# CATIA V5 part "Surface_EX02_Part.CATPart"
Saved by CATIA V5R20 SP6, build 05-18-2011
Part number: Surface_EX02_Part
Bounding box of the stored display mesh (mm): x -11.2 to 32.635, y -54.492 to 10.43, z -5 to 39.701
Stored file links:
  C:\Work\#01 CATIA Lecture Materials\#299 TOYOTA CATIA V5\TOYOTA_CATIA\LCS\Surface\Surface EX02\Surface_EX02_Part.CATPart
  C:\Work\#01 CATIA Lecture Materials\#299 TOYOTA CATIA V5\TOYOTA_CATIA\LCS\Surface\Surface EX02\Surface_EX02.CATProduct
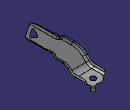
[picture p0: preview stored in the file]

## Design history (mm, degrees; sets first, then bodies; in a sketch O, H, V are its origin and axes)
Set1
  Point1: linked copy from another document
  Line1 to Line3: linked copy from another document
  Point2: linked copy from another document
  Line4 to Line6: linked copy from another document
Set2 "Base"
  Sketch1 on Line6, origin (25, -50, 35), H (0, 0.7071, 0.7071), V (0.5779, -0.5771, 0.5771)
    line L1 (0, 50) -> (0, -150)
    point P1 (0, 50)
    point P2 (0, -150)
    distance P1 P2 = 200
    distance H P2 = 150
    coincidence: P1 V
    vertical: L1 V
  Sketch2 on Line3, origin (0, 0, 0), H (0, 1, 0), V (0, 0, 1)
    line L1 (-150, 0) -> (50, 0)
    point P1 (-150, 0)
    point P2 (50, 0)
    distance P2 P1 = 200
    distance V P1 = 150
    coincidence: P1 H
    horizontal: L1 H
  Extrude1: Lim1 200, Lim2 200, Element1 Sketch2
  Extrude2: Lim1 200, Lim2 200, Element1 Sketch1
Set3 "Base Cut"
  Sketch3 on Line5, origin (25, -50, 35), H (-0.8161, -0.4086, 0.4086), V (0.5779, -0.5771, 0.5771)
    point P1 (-41.5, -30)
    line L1 (-41.5, -30) -> (-9.3787, 2.1213)
    point P2 (-8.5, 3)
    line L2 (-7.2574, 3) -> (7.2574, 3)
    point P3 (8.5, 3)
    line L3 (9.3787, 2.1213) -> (41.5, -30)
    point P4 (41.5, -30)
    arc A1 centre (-7.2574, 0) radius 3 from (-9.3787, 2.1213) to (-7.2574, 3) cw
    construction line L4 (-9.3787, 2.1213) -> (-8.5, 3)
    construction line L5 (-8.5, 3) -> (-7.2574, 3)
    arc A2 centre (7.2574, 0) radius 3 from (7.2574, 3) to (9.3787, 2.1213) cw
    construction line L6 (7.2574, 3) -> (8.5, 3)
    construction line L7 (8.5, 3) -> (9.3787, 2.1213)
    distance P2 P3 = 17
    distance L2 H = 3
    distance H P1 = 30
    distance H P4 = 30
    radius A1 = 3
    radius A2 = 3 {= Sketch3.radius(A1)}
    angle L2 L1 = 45
    angle L2 L3 = 45
    horizontal: L2 H
    symmetry: P2 P3 V
    coincidence: L1 P2, L2 P2, L1 L4, L2 L5, L2 P3, L3 P3, L2 L6, L3 L7
    tangency: A1 L1, A1 L2, A2 L2, A2 L3
  Sketch4 on Line3, origin (0, 0, 0), H (0, 1, 0), V (-1, 0, 0)
    arc A1 centre (0, 0) radius 8.5 from (7.9288, -3.0633) to (3.9391, 7.5322) ccw
    line L1 (2.8659, -10.8764) -> (2.8659, -50)
    construction line L2 (0, 0) -> (12.6476, -12.6476)
    line L3 (8.3802, -5.1982) -> (10.4298, -7.2478)
    line L4 (10.4298, -7.2478) -> (7.2478, -10.4298)
    line L5 (7.2478, -10.4298) -> (6.2802, -9.4621)
    reference projected point E1 (0, 0) from Point1
    point P4 (2.8659, 8.0023)
    point P5 (2.8659, -50)
    arc A2 centre (4.8659, -10.8764) radius 2 from (6.2802, -9.4621) to (2.8659, -10.8764) ccw
    construction line L6 (6.2802, -9.4621) -> (2.8659, -6.0479)
    construction line L7 (2.8659, -6.0479) -> (2.8659, -10.8764)
    line L8 (2.8659, 9.3044) -> (2.8659, 50)
    point P10 (2.8659, 50)
    arc A3 centre (4.8659, 9.3044) radius 2 from (3.9391, 7.5322) to (2.8659, 9.3044) cw
    construction arc A4 centre (0, 0) radius 8.5 from (3.9391, 7.5322) to (2.8659, 8.0023) ccw
    construction line L9 (2.8659, 8.0023) -> (2.8659, 9.3044)
    arc A5 centre (9.7944, -3.784) radius 2 from (7.9288, -3.0633) to (8.3802, -5.1982) ccw
    construction arc A6 centre (0, 0) radius 8.5 from (7.387, -4.205) to (7.9288, -3.0633) ccw
    construction line L10 (7.387, -4.205) -> (8.3802, -5.1982)
    radius A1 = 8.5
    distance L1 V = 2.8659
    angle L2 H = 45
    distance L3 L5 = 4.5
    distance L4 E1 = 12.5
    radius A2 = 2
    radius A3 = 2
    radius A5 = 2
    distance H P10 = 50
    distance P5 H = 50
    vertical: L1 V
    perpendicularity: L4 L3
    parallelism: L5 L2
    symmetry: L3 L5 L2
    coincidence: P4 L1, L5 L6, L1 L7, A1 P4, L8 P4, A1 A4, L8 L9, A1 A6, L3 L10
    tangency: A2 L5, A2 L1, L8 A2, A3 A1, A3 L8, A5 A1, A5 L3
  Extrude3: Lim1 200, Lim2 200, Element1 Sketch3
  Extrude4: Lim1 200, Lim2 200, Element1 Sketch4
Set4 "Flange"
  Sketch5 on Line5, origin (25, -50, 35), H (-0.8161, -0.4086, 0.4086), V (0.5779, -0.5771, 0.5771)
    point P1 (-8.5, 30)
    line L1 (-8.5, 30) -> (-8.5, -23.7574)
    point P2 (-8.5, -25)
    line L2 (-9.3787, -25.8787) -> (-10.3213, -26.8213)
    line L3 (-11.2, -28.9426) -> (-11.2, -150)
    point P3 (-11.2, -150)
    arc A1 centre (-11.5, -23.7574) radius 3 from (-8.5, -23.7574) to (-9.3787, -25.8787) cw
    construction line L4 (-8.5, -23.7574) -> (-8.5, -25)
    construction line L5 (-8.5, -25) -> (-9.3787, -25.8787)
    arc A2 centre (-8.2, -28.9426) radius 3 from (-10.3213, -26.8213) to (-11.2, -28.9426) ccw
    construction line L6 (-10.3213, -26.8213) -> (-11.2, -27.7)
    construction line L7 (-11.2, -27.7) -> (-11.2, -28.9426)
    distance H P1 = 30
    distance H P2 = 25
    angle L2 L3 = 45
    distance V L1 = 8.5
    distance V L3 = 11.2
    distance H P3 = 150
    radius A1 = 3
    radius A2 = 3
    vertical: L1 V, L3 V
    coincidence: L1 P2, L2 P2, L1 L4, L2 L5, L2 L6, L3 L7
    tangency: A1 L1, A1 L2, A2 L2, A2 L3
  Sketch6 on Line5, origin (25, -50, 35), H (-0.8161, -0.4086, 0.4086), V (0.5779, -0.5771, 0.5771)
    point P1 (8.5, 30)
    line L1 (8.5, 30) -> (8.5, -23.7574)
    point P2 (8.5, -25)
    line L2 (9.3787, -25.8787) -> (10.3213, -26.8213)
    line L3 (11.2, -28.9426) -> (11.2, -150)
    point P3 (11.2, -150)
    arc A1 centre (11.5, -23.7574) radius 3 from (8.5, -23.7574) to (9.3787, -25.8787) ccw
    construction line L4 (8.5, -23.7574) -> (8.5, -25)
    construction line L5 (8.5, -25) -> (9.3787, -25.8787)
    arc A2 centre (8.2, -28.9426) radius 3 from (10.3213, -26.8213) to (11.2, -28.9426) cw
    construction line L6 (10.3213, -26.8213) -> (11.2, -27.7)
    construction line L7 (11.2, -27.7) -> (11.2, -28.9426)
    distance V L1 = 8.5
    distance V L3 = 11.2
    distance H P1 = 30
    distance H P2 = 25
    angle L2 L3 = 45
    distance H P3 = 150
    radius A1 = 3
    radius A2 = 3 {= Sketch6.radius(A1)}
    vertical: L1 V, L3 V
    coincidence: L1 P2, L2 P2, L1 L4, L2 L5, L2 L6, L3 L7
    tangency: A1 L1, A1 L2, A2 L2, A2 L3
  Extrude5: Lim1 200, Lim2 200, Element1 Sketch5
  Extrude6: Lim1 100, Lim2 150, Element1 Sketch6
  Sketch7 on Line3, origin (0, 0, 0), H (0, 1, 0), V (-1, 0, 0)
    line L1 (-150, 11.2) -> (50, 11.2)
    point P1 (-150, 11.2)
    point P2 (50, 11.2)
    distance P2 P1 = 200
    distance V P1 = 150
    distance H L1 = 11.2
    horizontal: L1 H
  Sketch8 on Line3, origin (0, 0, 0), H (0, 1, 0), V (-1, 0, 0)
    line L1 (-150, -11.2) -> (50, -11.2)
    point P1 (-150, -11.2)
    point P2 (50, -11.2)
    distance P2 P1 = 200
    distance V P1 = 150
    distance H L1 = 11.2
    horizontal: L1 H
  Extrude7: Lim1 200, Lim2 200, Element1 Sketch8
  Extrude8: Lim1 200, Lim2 200, Element1 Sketch7
Set5 "Flange Cut"
  Sketch9 on Line4, origin (25, -50, 35), H (-0.5779, 0.5771, -0.5771), V (0, 0.7071, 0.7071)
    point P1 (-30, -30)
    line L1 (-30, -30) -> (2.1213, 2.1213)
    point P2 (3, 3)
    line L2 (4.2426, 3) -> (16.7574, 3)
    line L3 (18.8787, 3.8787) -> (19.1213, 4.1213)
    point P3 (20, 5)
    line L4 (21.2426, 5) -> (150, 5)
    point P4 (150, 5)
    arc A1 centre (16.7574, 6) radius 3 from (16.7574, 3) to (18.8787, 3.8787) ccw
    construction line L5 (16.7574, 3) -> (18, 3)
    construction line L6 (18, 3) -> (18.8787, 3.8787)
    arc A2 centre (21.2426, 2) radius 3 from (19.1213, 4.1213) to (21.2426, 5) cw
    construction line L7 (19.1213, 4.1213) -> (20, 5)
    construction line L8 (20, 5) -> (21.2426, 5)
    arc A3 centre (4.2426, 0) radius 3 from (2.1213, 2.1213) to (4.2426, 3) cw
    construction line L9 (2.1213, 2.1213) -> (3, 3)
    construction line L10 (3, 3) -> (4.2426, 3)
    point P17 (-30, -30)
    construction line L11 (0, 0) -> (-30, -30)
    construction line L12 (0, 0) -> (-1.2426, 0)
    angle L3 L2 = 45
    distance V P2 = 3
    distance V P3 = 20
    distance H L4 = 5
    distance V P1 = 30
    distance V P4 = 150
    distance L2 H = 3
    radius A1 = 3
    radius A2 = 3 {= Sketch9.radius(A1)}
    radius A3 = 3 {= Sketch9.radius(A1)}
    angle L1 V = 45
    horizontal: L2 H, L4 H
    coincidence: L2 L5, L3 L6, L3 P3, L4 P3, L3 L7, L4 L8, L1 P2, L2 P2, L1 L9, L2 L10, P1 L1, L1 L11, P17 P1
    tangency: A1 L2, A1 L3, A2 L3, A2 L4, A3 L1, A3 L2
  Sketch10 on Line3, origin (0, 0, 0), H (0, 1, 0), V (0, 0, 1)
    point P1 (-100, 5)
    line L1 (-100, 5) -> (0, 5)
    line L2 (3, 2) -> (3, -100)
    point P2 (3, -100)
    arc A1 centre (0, 2) radius 3 from (0, 5) to (3, 2) cw
    construction line L3 (0, 5) -> (3, 5)
    construction line L4 (3, 5) -> (3, 2)
    distance L1 H = 5
    distance V L2 = 3
    distance V P1 = 100
    distance P2 H = 100
    radius A1 = 3
    vertical: L2 V
    horizontal: L1 H
    coincidence: L1 L3, L2 L4
    tangency: A1 L1, A1 L2
  Extrude9: Lim1 200, Lim2 200, Element1 Sketch9
  Extrude10: Lim1 200, Lim2 200, Element1 Sketch10
Set6 "Clip"
  Sketch11 on Line3, origin (0, 0, 0), H (0, 1, 0), V (-1, 0, 0)
    construction line L1 (0, 0) -> (8.8388, -8.8388)
    point P1 (8.8388, -8.8388)
    reference projected point E1 (0, 0) from Point1
    line L2 (1.7678, -15.9099) -> (15.9099, -1.7678)
    point P2 (1.7678, -15.9099)
    point P3 (15.9099, -1.7678)
    angle L1 H = 45
    distance P1 E1 = 12.5
    distance P3 P2 = 20
    perpendicularity: L2 L1
    symmetry: P3 P2 L1
    coincidence: L2 P1
  Extrude11: Lim1 200, Lim2 200, Element1 Sketch11
Set7 "Clip Cut"
  Plane1: type Angle, RefPlane {plane type 2Lines, Element1 Line3, Element2 Line1}, Direction Line1, Angle 45
  Plane2: type Offset, RefPlane Plane1, Offset 12.5
  Sketch12 on Plane2, origin (8.8388, 8.8388, 0), H (-0.7071, 0.7071, 0), V (0, 0, 1)
    line L1 (-2.25, 30) -> (-2.25, -4)
    line L2 (-1.25, -5) -> (1.25, -5)
    line L3 (2.25, -4) -> (2.25, 30)
    construction line L4 (2.25, 30) -> (-2.25, 30)
    arc A1 centre (-1.25, -4) radius 1 from (-2.25, -4) to (-1.25, -5) ccw
    construction line L5 (-2.25, -4) -> (-2.25, -5)
    construction line L6 (-2.25, -5) -> (-1.25, -5)
    arc A2 centre (1.25, -4) radius 1 from (1.25, -5) to (2.25, -4) ccw
    construction line L7 (1.25, -5) -> (2.25, -5)
    construction line L8 (2.25, -5) -> (2.25, -4)
    distance L3 L1 = 4.5
    distance L2 H = 5
    distance H L4 = 30
    radius A1 = 1
    radius A2 = 1 {= Sketch12.radius(A1)}
    vertical: L1 V, L3 V
    horizontal: L2 H, L4 H
    symmetry: L1 L3 V
    coincidence: L1 L5, L2 L6, L2 L7, L3 L8
    tangency: A1 L1, A1 L2, A2 L2, A2 L3
  Extrude12: Lim1 200, Lim2 200, Element1 Sketch12
Set8 "Hole"
  Sketch13 on Line3, origin (0, 0, 0), H (0, 1, 0), V (-1, 0, 0)
    circle A1 centre (0, 0) radius 3.4
    radius A1 = 3.4
  Extrude13: Lim1 200, Lim2 200, Element1 Sketch13
  Sketch14 on Line5, origin (25, -50, 35), H (-0.8161, -0.4086, 0.4086), V (0.5779, -0.5771, 0.5771)
    point P1 (-5.5, -0.3)
    line L1 (-2.7771, -0.3) -> (2.7771, -0.3)
    point P2 (5.5, -0.3)
    line L2 (4.045, -2.6015) -> (1.2679, -6.9944)
    point P3 (0, -9)
    line L3 (-1.2679, -6.9944) -> (-4.045, -2.6015)
    arc A1 centre (-2.7771, -1.8) radius 1.5 from (-4.045, -2.6015) to (-2.7771, -0.3) cw
    construction line L4 (-4.045, -2.6015) -> (-5.5, -0.3)
    construction line L5 (-5.5, -0.3) -> (-2.7771, -0.3)
    arc A2 centre (2.7771, -1.8) radius 1.5 from (2.7771, -0.3) to (4.045, -2.6015) cw
    construction line L6 (2.7771, -0.3) -> (5.5, -0.3)
    construction line L7 (5.5, -0.3) -> (4.045, -2.6015)
    arc A3 centre (0, -6.1929) radius 1.5 from (1.2679, -6.9944) to (-1.2679, -6.9944) cw
    construction line L8 (1.2679, -6.9944) -> (0, -9)
    construction line L9 (0, -9) -> (-1.2679, -6.9944)
    distance P1 P2 = 11
    distance H L1 = 0.3
    distance H P3 = 9
    radius A1 = 1.5
    radius A2 = 1.5 {= Sketch14.radius(A1)}
    radius A3 = 1.5 {= Sketch14.radius(A1)}
    horizontal: L1 H
    coincidence: P3 V, L3 P1, L1 P1, L3 L4, L1 L5, L1 P2, L2 P2, L1 L6, L2 L7, L2 P3, L3 P3, L2 L8, L3 L9
    symmetry: P1 P2 V
    tangency: A1 L3, A1 L1, A2 L1, A2 L2, A3 L2, A3 L3
  Extrude14: Lim1 200, Lim2 200, Element1 Sketch14
Set9 "Trim"
  Split1: ToCut Fillet1, Cutting (Extrude3; Extrude4)
  Split2: ToCut Split1, Cutting (Extrude14; Extrude13)
  Split3: ToCut Fillet2, Cutting Fillet1
  Split4: ToCut Split3, Cutting Fillet3
  Split5: ToCut Fillet4, Cutting Fillet1
  Split6: ToCut Split5, Cutting Fillet3
  Split7: ToCut Extrude11, Cutting Extrude12
Set10 "Fillet"
  Fillet1: type BiTangent, Element1 Extrude2, Element2 Extrude1, Radius 10
  Fillet2: type BiTangent, Element1 Extrude7, Radius 10, Element2 Extrude5
  Fillet3: type BiTangent, Element1 Extrude9, Element2 Extrude10, Radius 5
  Fillet4: type BiTangent, Element1 Extrude6, Radius 25, Element2 Extrude8, FacesToKeep (face of Extrude6 from Sketch6.L3; face of Extrude8 from Sketch7.L1)
  Fillet5: type BiTangent, Element1 Split4, Radius 2, Element2 Split2
  Fillet6: type BiTangent, Element1 Fillet5, Radius 2, Element2 Split6
  Fillet7: type BiTangent, Element1 Fillet6, Element2 Split7, Radius 1
Body1 (main body)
